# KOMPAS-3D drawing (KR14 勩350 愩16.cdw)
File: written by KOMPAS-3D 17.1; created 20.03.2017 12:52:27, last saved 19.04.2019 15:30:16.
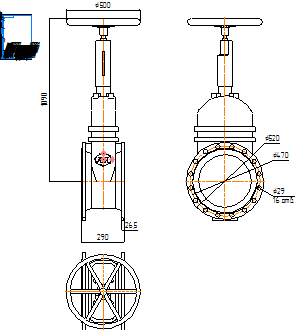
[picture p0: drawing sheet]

Sheet 1: A4, portrait

Title block, sheet 1: name: KR14 Ду350 Ру16; material: Внимание! Данный продукт является объектом авторского права ООО «Торговый Дом АДЛ». / Запрещается изменение, копирование, распространение / (в том числе путем копирования на другие сайты и ресурсы в Интернете) / или любое иное использование информации и объектов без предварительного / согласия правообладателя (ООО «Торговый Дом АДЛ»).; mass: 508; sheets: 1; organisation: ООО "Торговый дом АДЛ"; sheet format: A4; stored path: C:\Users\kka\KOMPAS_Work\!Trash\Задвижки ГРАНАР с приводами\KR14 Ду350 Ру16.cdw

Views: Вид 1, Проекционный вид 2, Проекционный вид 3
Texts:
  Klimkovich
  ADL
Dimensions and other numbers on the sheet: 290; 500; 1090; 26,5; 520; 470; 29; 16 отв.; 1:1; 1; 508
